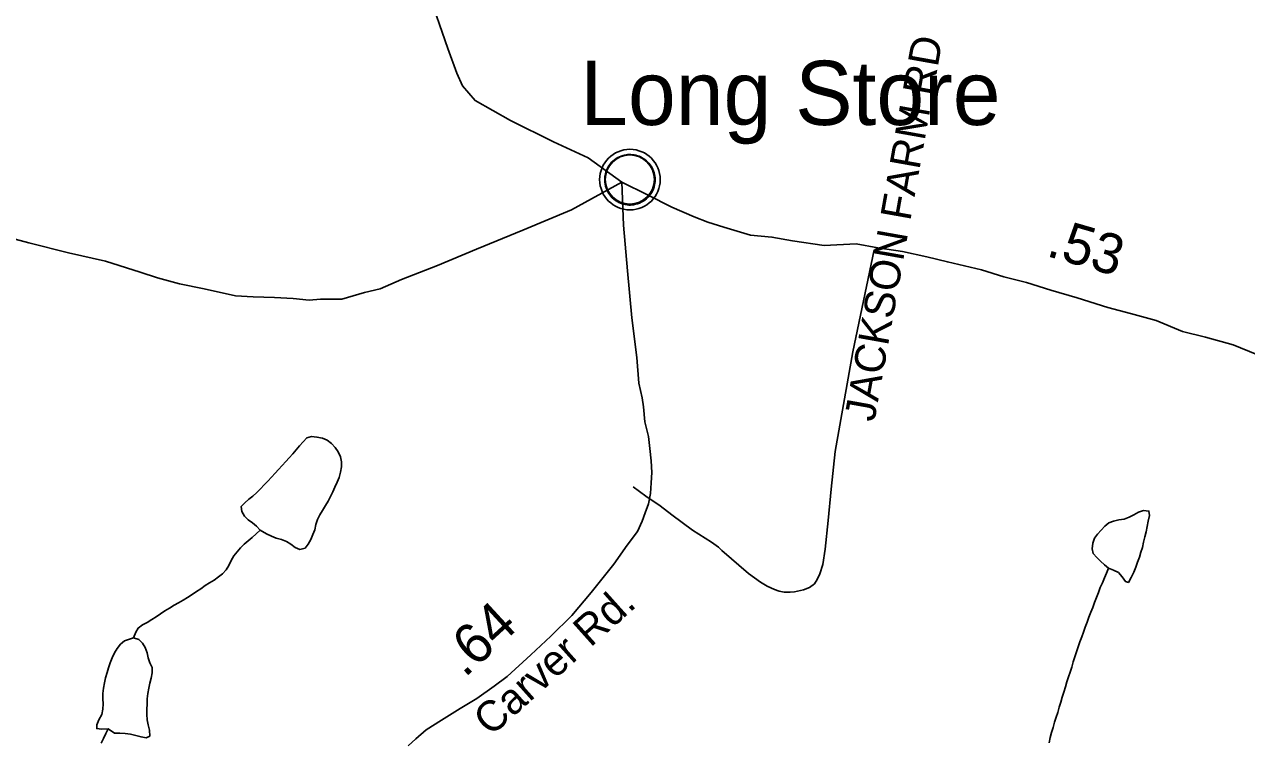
# Model space of a CAD drawing. Extents: x 1950930 to 2061844, y 904556 to 1017002.
# Drawn here: x 1975173 to 1978977, y 967930 to 970163 of the extents above; entities that cross this region are included whole.
import ezdxf

# ---------------------------------------------------------------- set-up
doc = ezdxf.new("R2010")
doc.units = 0
for name, color, linetype in [('Exist Civil Demographics Community CELL', 7, 'Continuous'), ('Exist Civil Demographics Community Label', 7, 'Continuous'), ('Exist Hydrographic Misc Water Feature', 7, 'Continuous'), ('Exist Road Non-System Type 51', 7, 'Continuous'), ('Exist Road Non-System Type 51 Label', 7, 'Continuous'), ('Exist Road Primary US Structure Standard Bridge CELL', 7, 'Continuous'), ('Exist Road Secondary Type 51 Attributed', 7, 'Continuous'), ('Exist Road Secondary Type 51 Label', 7, 'Continuous')]:
    doc.layers.add(name, color=color, linetype=linetype)

msp = doc.modelspace()

# ---------------------------------------------------------------- linework, layer by layer
at = {"layer": 'Exist Civil Demographics Community CELL'}
msp.add_lwpolyline([(1976980.4, 969692.5), (1976981.4, 969698), (1976983.1, 969704.6), (1976986.1, 969711.8), (1976989, 969717.6), (1976992.3, 969723.3), (1976996.1, 969728.4), (1977000, 969732.8), (1977004.6, 969737.4), (1977010.2, 969742), (1977015.6, 969745.6), (1977020.5, 969748.5), (1977025.5, 969751), (1977031, 969753.2), (1977036.6, 969755.1), (1977040.9, 969756.2), (1977045.8, 969757), (1977049.9, 969757.7), (1977056.3, 969757.9), (1977060.7, 969757.8), (1977066.4, 969757.6), (1977071.3, 969756.8), (1977076.2, 969755.9), (1977081.2, 969754.4), (1977086.4, 969752.5), (1977093, 969749.6), (1977099.3, 969746.1), (1977104.3, 969742.5), (1977109.5, 969738.5), (1977112.8, 969735.4), (1977116.9, 969731), (1977120.8, 969726.3), (1977123.9, 969721.7), (1977127, 969716.7), (1977129.5, 969711.6), (1977131.5, 969706.5), (1977133.1, 969701.5), (1977134.3, 969696.9), (1977135.4, 969690.9), (1977136.1, 969686.2), (1977136.3, 969680.2), (1977136.1, 969674.4), (1977135.6, 969668.7), (1977134.6, 969663.2), (1977133, 969657.1), (1977131.1, 969651.2), (1977128.8, 969646.2), (1977125.7, 969640.2), (1977122.4, 969634.9), (1977118.9, 969630.2), (1977114.7, 969625.4), (1977109.4, 969620.5), (1977104.4, 969616.3), (1977099.4, 969612.9), (1977095.1, 969610.4), (1977088.2, 969607.1), (1977081.1, 969604.4), (1977075.2, 969603), (1977068.6, 969601.7), (1977064.1, 969601.2), (1977059.6, 969600.9), (1977054, 969600.9), (1977049.8, 969601.4), (1977044.1, 969602.1), (1977038.2, 969603.4), (1977033.6, 969604.7), (1977028.5, 969606.6), (1977023.9, 969608.6), (1977019.9, 969610.8), (1977013.1, 969614.9), (1977007.6, 969619.1), (1977002.6, 969623.6), (1976998.2, 969628.5), (1976995, 969632.5), (1976992, 969636.6), (1976987.9, 969643.7), (1976986.2, 969647.3), (1976984.5, 969651.3), (1976981.9, 969659.5), (1976980.4, 969666.5), (1976979.7, 969671.7), (1976979.4, 969678), (1976979.3, 969682.7), (1976979.8, 969689.2)], close=True, dxfattribs=at)
for centre, radius in [((1977058, 969680), 94.3), ((1977057.7, 969680.3), 76.7)]:
    msp.add_circle(centre, radius, dxfattribs=at)
at = {"layer": 'Exist Hydrographic Misc Water Feature'}
for points in [[(1975906.7, 968588.3), (1975895.8, 968600.8), (1975883.3, 968611), (1975869.4, 968620.3), (1975858.1, 968632), (1975849.7, 968646.2), (1975847.8, 968661.7), (1975859.5, 968673), (1975871.8, 968684.3), (1975884.3, 968694.6), (1975896.4, 968705.9), (1975908.3, 968717.1), (1975919.6, 968729.2), (1975930.9, 968741.3), (1975942.2, 968753.3), (1975953.4, 968765.5), (1975964.5, 968777.5), (1975975.6, 968789.6), (1975986.5, 968801.7), (1975997.7, 968813.8), (1976008.6, 968825.8), (1976019.1, 968838.8), (1976029.7, 968850.8), (1976040.8, 968863.7), (1976052.5, 968875.8), (1976067, 968879.6), (1976083.9, 968878.4), (1976100.9, 968874.8), (1976115.8, 968868.7), (1976129, 968858.6), (1976140.4, 968846.1), (1976149.7, 968832.7), (1976156.8, 968817), (1976160.5, 968801.3), (1976159.9, 968785), (1976156.8, 968768.6), (1976152.5, 968752.3), (1976147, 968737.6), (1976139.8, 968722.2), (1976133.1, 968707.6), (1976125.7, 968692.9), (1976118.3, 968678.3), (1976109.9, 968664.6), (1976101.1, 968649.9), (1976092.7, 968636.2), (1976085.1, 968621.5), (1976080.4, 968606.1), (1976077.1, 968589.8), (1976071.3, 968574.3), (1976064.4, 968558.8), (1976056.2, 968544.2), (1976046.9, 968532.1), (1976030.5, 968528.3), (1976016, 968534.4), (1976002.9, 968544.5), (1975988.5, 968553), (1975973.1, 968559.1), (1975957.3, 968563.5), (1975942.2, 968569.6), (1975927.2, 968576.4), (1975906.7, 968588.3)], [(1978547.3, 968469.7), (1978535.2, 968480.6), (1978522.9, 968491.5), (1978511.3, 968503.2), (1978499.6, 968515.8), (1978496.5, 968530.6), (1978498.5, 968547.8), (1978503.5, 968563.3), (1978513.3, 968576.2), (1978524.8, 968588.3), (1978536.1, 968601.2), (1978548.8, 968610.8), (1978563.5, 968616.2), (1978580, 968620), (1978596.4, 968622.9), (1978611.7, 968628.3), (1978626.5, 968636.3), (1978640.9, 968644.2), (1978656.4, 968649.6), (1978673.2, 968647.6), (1978674.7, 968633.6), (1978671.4, 968616.4), (1978667.5, 968599.3), (1978664.4, 968583), (1978660.7, 968567.5), (1978656.8, 968551.1), (1978652.9, 968534.8), (1978648.4, 968519.3), (1978643.7, 968503.7), (1978638.2, 968488.4), (1978632.2, 968472.9), (1978625.9, 968457.4), (1978618.5, 968441.1), (1978609.7, 968425.7), (1978600, 968428.4), (1978589.8, 968443.4), (1978578.3, 968456.8), (1978563.5, 968463.6), (1978547.3, 968469.7)], [(1975906.7, 968588.3), (1975894.6, 968577.2), (1975882.1, 968565.9), (1975870, 968555.4), (1975857.7, 968544.2), (1975846.2, 968533), (1975835.1, 968520.9), (1975825.3, 968507.9), (1975817.1, 968493.4), (1975809.3, 968478.7), (1975800.7, 968465), (1975790.2, 968452.1), (1975777.3, 968442.5), (1975763.6, 968432.9), (1975749.4, 968424.3), (1975735.9, 968415.5), (1975722.3, 968405.9), (1975708.6, 968397.2), (1975694.9, 968387.6), (1975681.1, 968378.9), (1975667.2, 968370.2), (1975653, 968362.2), (1975638.9, 968354.3), (1975624.5, 968345.5), (1975610.6, 968336.8), (1975596.9, 968328.1), (1975583.3, 968318.6), (1975569.6, 968309.8), (1975555.6, 968301), (1975540.7, 968293.2), (1975527.5, 968283.5), (1975519.5, 968270.6), (1975513.2, 968252.7)], [(1978547.3, 968469.7), (1978541, 968454.2), (1978534.8, 968439.6), (1978528.5, 968424.2), (1978521.9, 968409.5), (1978516, 968394), (1978509.8, 968378.6), (1978504.1, 968363.1), (1978498.3, 968347.6), (1978492.4, 968332.9), (1978486.4, 968317.6), (1978480.9, 968302), (1978475.2, 968286.6), (1978469.6, 968271.1), (1978464.1, 968255.6), (1978458.8, 968240.1), (1978453.2, 968224.7), (1978448.1, 968209.2), (1978443, 968193.7), (1978437.8, 968178.2), (1978432.9, 968161.9), (1978427.8, 968146.4), (1978423.1, 968131), (1978418.2, 968115.5), (1978413.4, 968100), (1978408.7, 968083.6), (1978403.8, 968068.1), (1978399.3, 968052.6), (1978394.4, 968037.1), (1978389.9, 968020.8), (1978384.9, 968005.4), (1978379.8, 967989.9), (1978375.3, 967973.6), (1978370.6, 967958.1), (1978366.1, 967942.6), (1978362.4, 967926.2)], [(1975433.4, 967969.6), (1975413.5, 967968.5), (1975398.2, 967970.4), (1975398.2, 967981.9), (1975405.3, 967997.3), (1975413.7, 968014.4), (1975417.8, 968030.7), (1975418, 968047.1), (1975417.4, 968063.5), (1975417.4, 968079.9), (1975419.5, 968096.3), (1975422.6, 968112.6), (1975426, 968128.2), (1975430.4, 968144.5), (1975435.1, 968160), (1975440.4, 968175.5), (1975446.5, 968190.9), (1975453.7, 968206.3), (1975462.1, 968220.2), (1975472.2, 968233.1), (1975484.9, 968243.4), (1975513.2, 968252.7)], [(1975513.2, 968252.7), (1975529, 968247.4), (1975540.5, 968236.6), (1975549.3, 968222.4), (1975555.2, 968206.6), (1975558.1, 968191), (1975564, 968175.4), (1975570.6, 968160.4), (1975570.8, 968144), (1975567.5, 968127.7), (1975563.8, 968111.4), (1975560.6, 968095.8), (1975557.3, 968079.5), (1975555.6, 968063.1), (1975554.8, 968046.7), (1975554.2, 968030.3), (1975554.4, 968013.9), (1975555.4, 967997.5), (1975558.9, 967981.8), (1975562.2, 967965.4), (1975563.2, 967947.2), (1975552.2, 967941.7), (1975536.6, 967944.6), (1975520, 967949), (1975503.1, 967953.4), (1975486.7, 967955.4), (1975469.9, 967955.7), (1975453.3, 967956.2), (1975433.4, 967969.6)], [(1975433.4, 967969.6), (1975426.5, 967955), (1975419.7, 967939.5), (1975412.5, 967924.9)]]:
    msp.add_lwpolyline(points, dxfattribs=at)
at = {"layer": 'Exist Road Non-System Type 51'}
msp.add_lwpolyline([(1977818, 969461.4), (1977752.2, 969144), (1977697.1, 968833.2), (1977684.1, 968715.6), (1977674.8, 968618.6), (1977665.4, 968528.9), (1977658, 968481.4), (1977648.6, 968452.4), (1977641.1, 968434.7), (1977632.8, 968421.6), (1977616.9, 968409.5), (1977598.2, 968402.1), (1977570.2, 968396.4), (1977557.1, 968395.5), (1977537.5, 968395.5), (1977522.6, 968398.3), (1977507.8, 968403.9), (1977485.2, 968414.2), (1977464.8, 968426.3), (1977427.4, 968453.4), (1977344.4, 968525.2), (1977333.1, 968535.5), (1977311.8, 968550.4), (1977252.9, 968588.7), (1977188.5, 968636.3), (1977152.1, 968664.3), (1977107.4, 968694.2), (1977068.2, 968722.7)], dxfattribs=at)
at = {"layer": 'Exist Road Secondary Type 51 Attributed'}
for points in [[(1977032.8, 969671.7), (1976928.1, 969747.9), (1976820.2, 969798), (1976686.1, 969864.2), (1976576.1, 969926.1), (1976536.3, 969972.3), (1976518.9, 970011.7), (1976491, 970087.9), (1976429.5, 970266.1)], [(1975031.8, 969524.2), (1975187.1, 969483.5), (1975310.5, 969451.9), (1975426, 969425.7), (1975533.2, 969391.9), (1975587.5, 969374.4), (1975655.7, 969355.2), (1975732.7, 969339.4), (1975830.7, 969318.4), (1975885, 969314.9), (1975951.5, 969313.1), (1976009.3, 969309.6), (1976060, 969304.4), (1976095, 969307.9), (1976161.5, 969307.9), (1976231.5, 969328.9), (1976280.5, 969339.4), (1976347, 969369.2), (1976459, 969413), (1976580.7, 969462.9), (1976724.2, 969522.4), (1976876.4, 969585.5), (1977032.8, 969671.7)], [(1977032.8, 969671.7), (1977038, 969538), (1977049.9, 969396.1), (1977063.9, 969250), (1977079.9, 969126), (1977085.9, 969046), (1977095.9, 969000.2), (1977099.7, 968972.1), (1977103.8, 968926), (1977115.6, 968880), (1977119.7, 968842.1), (1977123.7, 968804), (1977125.7, 968768.1), (1977123.7, 968736.1), (1977121.6, 968702), (1977115.7, 968670.1), (1977105.7, 968642.1), (1977095.6, 968616.1), (1977081.5, 968584.2), (1977049.6, 968542), (1977007.6, 968482.1), (1976937.5, 968394.1), (1976877.4, 968322.1), (1976811.5, 968258.2), (1976749.4, 968200.3), (1976675.4, 968132.2), (1976635.4, 968102.2), (1976581.4, 968064.3), (1976529.3, 968032.4), (1976471.3, 967996.4), (1976423.3, 967966.4), (1976391.3, 967938.4), (1976367.2, 967916.5)], [(1977032.8, 969671.7), (1977112.3, 969632.6), (1977188, 969594.1), (1977258, 969564.5), (1977300.1, 969547.3), (1977350.7, 969531.9), (1977433.5, 969506.8), (1977500, 969501.1), (1977563.5, 969489.5), (1977662.3, 969474.7), (1977762.1, 969479.8), (1977830, 969467.6), (1977906, 969455.6), (1977981.9, 969439.6), (1978046, 969423.5), (1978151.9, 969399.5), (1978221.9, 969377.4), (1978292, 969359.6), (1978367.9, 969335.4), (1978449.8, 969311.5), (1978545.8, 969281.3), (1978615.9, 969263.4), (1978695.8, 969241.4), (1978777.8, 969207.3), (1978849.8, 969189.2), (1978935.7, 969165.2), (1979009.7, 969135.2)]]:
    msp.add_lwpolyline(points, dxfattribs=at)

# ---------------------------------------------------------------- texts
at = {"layer": 'Exist Civil Demographics Community Label'}
msp.add_text('Long Store', height=200, dxfattribs=at).set_placement((1976903.1, 969850.1))
at = {"layer": 'Exist Road Non-System Type 51 Label'}
msp.add_text('  JACKSON FARM RD', height=95, rotation=79.8771, dxfattribs=at).set_placement((1977806.2, 968853.8))
at = {"layer": 'Exist Road Primary US Structure Standard Bridge CELL'}
for s, rotation, p in [('.53', 343.7351, (1978350.2, 969443.2)), ('.64', 42.6061, (1976543.3, 968126.6))]:
    msp.add_text(s, height=125, rotation=rotation, dxfattribs=at).set_placement(p)
at = {"layer": 'Exist Road Secondary Type 51 Label'}
msp.add_text('Carver Rd.', height=95, rotation=41.8058, dxfattribs=at).set_placement((1976624.5, 967943.6))

doc.saveas('drawing.dxf')
